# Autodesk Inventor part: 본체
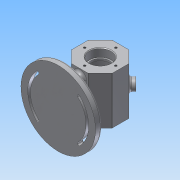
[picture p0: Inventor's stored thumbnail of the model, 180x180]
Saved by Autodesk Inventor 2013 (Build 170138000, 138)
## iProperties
Created: 2017-06
Part Number: 본체
Material: 알루미늄 6061
Document SubType Name: Modeling
Designer: Administrator
Density: 2.71 g/cm^3
Mass: 562.243 g
Surface Area: 566.162 cm^2
Volume: 207.47 cm^3
Author: Administrator
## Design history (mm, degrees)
sketch "스케치1" dims "d0" = 60
  geometry: L1 (12.426, 92)-(30, 74.426); L2 (30, 74.426)-(30, 49.574); L3 (30, 49.574)-(12.426, 32); L4 (12.426, 32)-(-12.426, 32); L5 (-12.426, 32)-(-30, 49.574); L6 (-30, 49.574)-(-30, 74.426); L7 (-30, 74.426)-(-12.426, 92); L8 (-12.426, 92)-(12.426, 92); 4 further points
  constraints: 16 end point, 3 vertical alignment, 1 coincident, 1 midpoint, 19 other
  dimensions: "d1" = 62 distance of point (0, 0) point (0, 62)
extrude "돌출1" new body sketch "스케치1" distance "d2" = 35; taper "d3" = 0 deg
sketch "스케치2"
  geometry: L1 (30, 74.426)-(12.426, 92) reference; 2 further points
  constraints: 1 vertical alignment
  dimensions: "d4" = 62 distance of point (0, 0) point (0, 62)
hole "구멍1" sketch "스케치2" at (0, 62) diameter "d5" = 28; stored, may be unused: countersink angle "d9" = 90 deg, drill point angle "d11" = 0 deg; dims "d6" = 6, "d7" = 32, "d8" = 12, "d10" = 15
sketch "스케치3"
  geometry: 2 further points
  constraints: 1 vertical alignment
  dimensions: "d12" = 62 distance of point (0, 0) point (0, 62)
hole "구멍2" sketch "스케치3" at (0, 62) diameter "d13" = 50; stored, may be unused: countersink angle "d17" = 90 deg, drill point angle "d19" = 0 deg; dims "d14" = 6, "d15" = 32, "d16" = 12, "d18" = 20
sketch "스케치4"
  geometry: L1 (30, 74.426)-(30, 49.574) reference; L2 (30, 49.574)-(12.426, 32) reference; L3 (12.426, 32)-(-12.426, 32) reference; L4 (-12.426, 32)-(-30, 49.574) reference; L5 (-30, 49.574)-(-30, 74.426) reference; L6 (-30, 74.426)-(-12.426, 92) reference; L7 (-12.426, 92)-(12.426, 92) reference; L8 (12.426, 92)-(30, 74.426) reference; C1 r 16 at (0, 62) reference; C2 r 16 at (0, 62) reference; 2 further points
  constraints: 1 vertical alignment
  dimensions: "d20" = 23 distance of C1.centre point (0, 85)
hole "구멍3" sketch "스케치4" at (0, 85) diameter "d21" = 3.242; stored, may be unused: countersink angle "d25" = 90 deg, drill point angle "d27" = 118 deg; dims "d22" = 8, "d23" = 32, "d24" = 12, "d26" = 10
chamfer "모따기1" distance "d31" = 1; stored, may be unused: second distance "d32" = 2, angle "d33" = 45 deg
fillet "모깎기1" dims "d34" = 0.3, "d35" = 3
sketch "스케치5"
  geometry: L1 (0, 0)-(70.711, 0); L2 (0, 0)-(77.782, 0); L3 (0, 55)-(0, -55); C1 r 43 at (0, 0); A1 r 55 centre (0, 0) between (0, 55) and (0, -55); A2 r 48 centre (0, 0) between (-33.941, 33.941) and (-33.941, -33.941); A3 r 38 centre (0, 0) between (-26.87, 26.87) and (-26.87, -26.87); A4 r 5 centre (-30.406, 30.406) between (-26.87, 26.87) and (-33.941, 33.941); A5 r 5 centre (-30.406, -30.406) between (-33.941, -33.941) and (-26.87, -26.87); A6 r 2 centre (-30.406, -30.406) between (-31.82, -31.82) and (-28.991, -28.991); A7 r 45 centre (0, 0) between (-31.82, 31.82) and (-31.82, -31.82); A8 r 2 centre (-30.406, 30.406) between (-28.991, 28.991) and (-31.82, 31.82); A9 r 41 centre (0, 0) between (-28.991, 28.991) and (-28.991, -28.991); 2 further points
  constraints: 19 point on circle, 10 centre point, 6 end point, 4 coincident, 2 horizontal, 1 horizontal alignment, 1 perpendicular, 1 vertical alignment
  dimensions: "d36" = 110 diameter of A1; "d39" = 76 diameter of A3; "d42" = 10 diameter of A4; "d43" = 10 diameter of A5; "d44" = 48 radius of A2; "d49" = 15.70796 dimension on point (0, 0) A5.centre A4.centre; "d51" = 7.85398 dimension on point (0, 0) point (-38, 0) A4.centre; "d52" = 3 radial gap between concentric circles of A9 A3; "d53" = 45 radius of A7; "d54" = 2 radius of A8; "d55" = 2 radius of A6; "d60" = 110 distance of L3.start L3.end; "d66" = 86 diameter of C1
extrude "돌출2" join sketch "스케치5" distance "d56" = 10; taper "d57" = 0 deg
extrude "돌출3" join sketch "스케치5" distance "d58" = 7; taper "d59" = 0 deg
sketch "스케치6"
  geometry: L1 (5, -29)-(-5, -29); L2 (-5, -29)-(-5, 29); L3 (-5, 29)-(5, 29); L4 (5, 29)-(5, -29); L5 (5, -29)-(-5, 29); L6 (-5, -29)-(5, 29); C1 r 55 at (0, 0) reference
  constraints: 12 end point, 2 midpoint, 2 parallel, 1 horizontal, 1 perpendicular
  dimensions: "d61" = 10 distance of L2.end L3.end; "d62" = 58 distance of L1.end L2.end
extrude "돌출4" join sketch "스케치6" stored distance "d63" = 7; taper "d64" = 0 deg
fillet "모깎기2" dims "d65" = 5
sketch "스케치8"
  geometry: L1 (-55, 0)-(-55, 10) reference; L2 (-55, 10)-(-48, 10) reference; L3 (-48, 10)-(-48, 7) reference; L4 (-48, 7)-(-45, 7) reference; L5 (-45, 7)-(-45, 0) reference; L6 (-45, 0)-(-55, 0) reference; L7 (55, 10)-(55, 0) reference; L8 (55, 0)-(45, 0) reference; L9 (45, 0)-(45, 7) reference; L10 (45, 7)-(48, 7) reference; L11 (48, 7)-(48, 10) reference; L12 (48, 10)-(55, 10) reference; L13 (30, 74.426)-(30, 49.574) reference; L14 (30, 49.574)-(12.426, 32) reference; L15 (12.426, 32)-(5, 32) reference; L16 (5, 32)-(5, 10) reference; L17 (5, 10)-(38, 10) reference; L18 (38, 10)-(38, 7) reference; L19 (38, 7)-(41, 7) reference; L20 (41, 7)-(41, 0) reference; L21 (41, 0)-(-41, 0) reference; L22 (-41, 0)-(-41, 7) reference; L23 (-41, 7)-(-38, 7) reference; L24 (-38, 7)-(-38, 10) reference; L25 (-38, 10)-(-5, 10) reference; L26 (-5, 10)-(-5, 32) reference; L27 (-5, 32)-(-12.426, 32) reference; L28 (-12.426, 32)-(-30, 49.574) reference; L29 (-30, 49.574)-(-30, 74.426) reference; L30 (-30, 74.426)-(-12.426, 92) reference; L31 (-12.426, 92)-(12.426, 92) reference; L32 (12.426, 92)-(30, 74.426) reference; L33 (0, 62)-(26.163, 88.163); L34 (0, 62)-(37, 62); C1 r 25 at (0, 62) reference; 1 further point
  constraints: 4 end point, 1 equal length, 1 horizontal, 1 perpendicular
  dimensions: "d72" = 37 distance of L33.start L33.end; "d73" = 45 deg angle of L34 L33 (derived)
  node "절단 모서리 투영2"
node "작업 평면2"
sketch "스케치9"
  geometry: L1 (-12.426, 35)-(12.426, 35) reference; C1 r 8 at (0, 0); 4 further points
  constraints: 1 centre point, 1 coincident
  dimensions: "d74" = 16 diameter of C1
extrude "돌출5" join sketch "스케치9" stored distance "d76" = 7; taper "d77" = 0 deg
hole "구멍4" diameter "d80" = 8; stored, may be unused: countersink angle "d84" = 90 deg, drill point angle "d86" = 0 deg; dims "d78" = 10, "d79" = 10, "d81" = 8, "d82" = 32, "d83" = 12, "d85" = 10
chamfer "모따기2" distance "d87" = 1; stored, may be unused: second distance "d88" = 2, angle "d89" = 45 deg
sketch "스케치10"
  geometry: L1 (0, 0)-(-17.574, 0) reference; L2 (-17.574, 0)-(-17.574, 70) reference; 2 further points
  constraints: 1 other
  dimensions: "d90" = 35 distance from line of L1 point (12.426, 35); "d91" = 30 distance from line of L2 point (12.426, 35)
feature "엠보싱1" sketch "스케치10" dims "d92" = 0.5, "d93" = 0
fillet "모깎기3" dims "d94" = 1, "d95" = 5, "d96" = 3
node "솔리드1"
pattern_circular "원형 패턴1" dims angle "d29" = 360 deg
mirror "대칭1"
mirror "대칭2"
node "절단 모서리 투영1"
